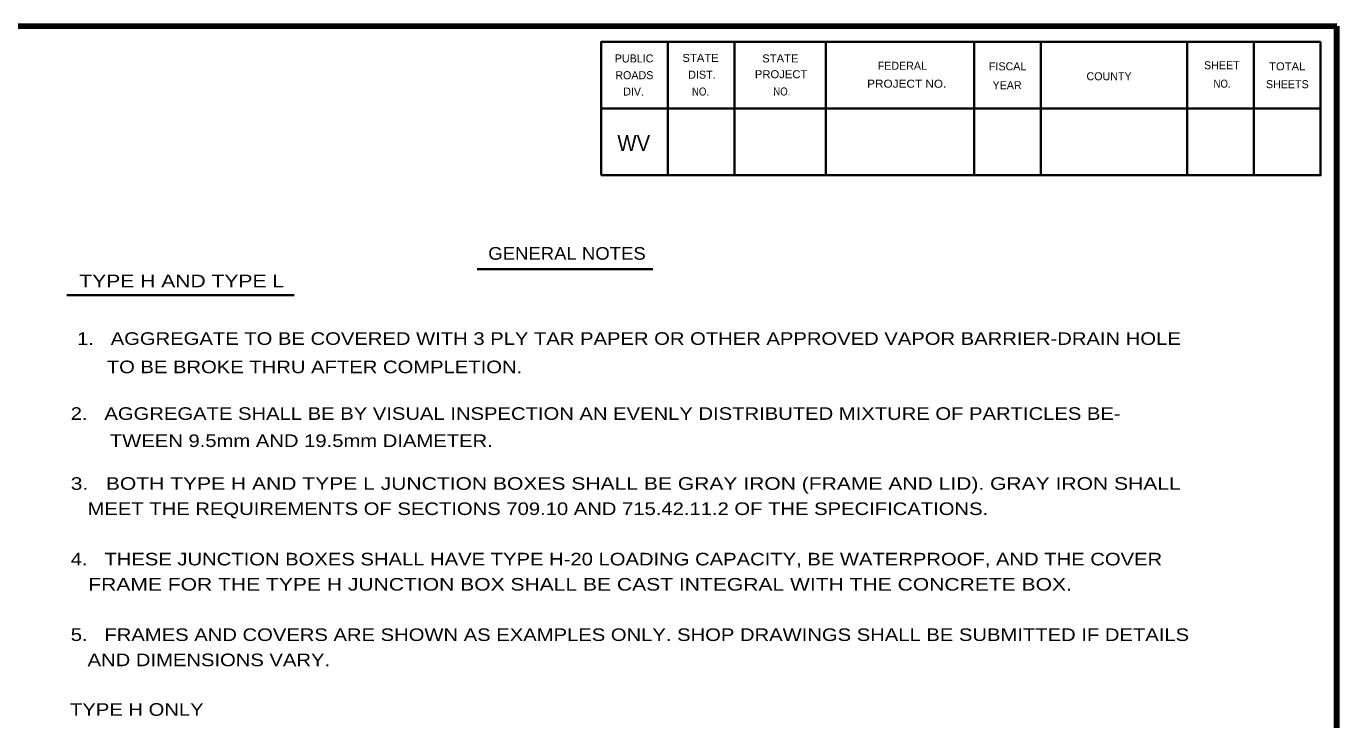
# Model space of a CAD drawing. Extents: x 442 to 1297, y -1132 to -588.
# Drawn here: x 1041 to 1290.7, y -726.2 to -594.1 of the extents above; entities that cross this region are included whole.
import ezdxf

# ---------------------------------------------------------------- set-up
doc = ezdxf.new("R2010")
doc.units = 0
doc.header["$LTSCALE"] = 0.96
doc.layers.add('1', color=7, linetype='Continuous', lineweight=35)
doc.layers.add('61', color=7, linetype='Continuous', lineweight=35)

msp = doc.modelspace()

# ---------------------------------------------------------------- linework, layer by layer
at = {"layer": '1', "lineweight": 158}
msp.add_line((1290.7447, -1120.1679), (1290.7447, -594.0679), dxfattribs=at)
at = {"layer": '1', "lineweight": 13}
msp.add_line((1290.7447, -1120.1679), (1290.7447, -594.0679), dxfattribs=at)
at = {"layer": '1'}
for p, q in [((1126.9354, -640.3295), (1160.3767, -640.3295)), ((1048.7097, -645.2843), (1092.0302, -645.2843))]:
    msp.add_line(p, q, dxfattribs=at)
at = {"layer": '1', "lineweight": 158}
msp.add_lwpolyline([(1290.7447, -594.0679), (499.0447, -594.1679), (499.1447, -1120.1679)], dxfattribs=at)
at = {"layer": '61'}
for p, q in [((1163.2447, -597.0679), (1163.2447, -622.4679)), ((1175.9447, -597.0679), (1175.9447, -622.4679)), ((1193.3447, -597.0679), (1193.3447, -622.4679)), ((1221.6447, -597.0679), (1221.6447, -622.4679)), ((1234.3447, -597.0679), (1234.3447, -622.4679)), ((1262.2447, -597.0679), (1262.2447, -622.4679)), ((1274.9447, -597.0679), (1274.9447, -622.4679)), ((1287.6447, -609.7679), (1150.5447, -609.7679))]:
    msp.add_line(p, q, dxfattribs=at)
for points in [[(1287.6447, -597.0679), (1150.5447, -597.0679), (1150.5447, -622.4679)], [(1287.6447, -597.0679), (1287.6447, -622.4679), (1150.5447, -622.4679)]]:
    msp.add_lwpolyline(points, dxfattribs=at)

# ---------------------------------------------------------------- texts
at = {"layer": '1'}
for s, height, width, p in [('WV', 3.048, 0.95, (1153.6447, -617.8679)), ('GENERAL NOTES', 2.4, 1.1, (1129.0254, -638.5495)), ('TYPE H AND TYPE L', 2.4, 1.25, (1051.0982, -643.8028)), ('1.   AGGREGATE TO BE COVERED WITH 3 PLY TAR PAPER OR OTHER APPROVED VAPOR BARRIER-DRAIN HOLE', 2.4, 1.2, (1050.6505, -654.7757)), ('TO BE BROKE THRU AFTER COMPLETION.', 2.4, 1.2, (1056.3233, -660.1728)), ('2.   AGGREGATE SHALL BE BY VISUAL INSPECTION AN EVENLY DISTRIBUTED MIXTURE OF PARTICLES BE-', 2.4, 1.2, (1049.4543, -669.0629)), ('TWEEN 9.5mm AND 19.5mm DIAMETER.', 2.4, 1.2, (1056.92, -674.2358)), ('3.   BOTH TYPE H AND TYPE L JUNCTION BOXES SHALL BE GRAY IRON (FRAME AND LID). GRAY IRON SHALL', 2.4, 1.25, (1049.4543, -682.3929)), ('   MEET THE REQUIREMENTS OF SECTIONS 709.10 AND 715.42.11.2 OF THE SPECIFICATIONS.', 2.4, 1.2, (1049.4543, -687.1929)), ('4.   THESE JUNCTION BOXES SHALL HAVE TYPE H-20 LOADING CAPACITY, BE WATERPROOF, AND THE COVER', 2.4, 1.2, (1049.4543, -696.7929)), ('   FRAME FOR THE TYPE H JUNCTION BOX SHALL BE CAST INTEGRAL WITH THE CONCRETE BOX.', 2.4, 1.25, (1049.4543, -701.5929)), ('5.   FRAMES AND COVERS ARE SHOWN AS EXAMPLES ONLY. SHOP DRAWINGS SHALL BE SUBMITTED IF DETAILS', 2.4, 1.2, (1049.4543, -711.1929)), ('   AND DIMENSIONS VARY.', 2.4, 1.2, (1049.4543, -715.9929)), ('TYPE H ONLY', 2.4, 1.2, (1049.3172, -725.4441))]:
    msp.add_text(s, height=height, dxfattribs=dict(at, width=width)).set_placement(p)
at = {"layer": '61'}
for s, height, rotation, p in [('PUBLIC', 1.525, 0.033, (1153.1447, -600.9679)), ('FEDERAL', 1.523, 0.007, (1203.2447, -602.3679)), ('FISCAL', 1.525, 359.942, (1224.4447, -602.4679)), ('SHEET', 1.525, 0.059, (1265.4447, -602.2679)), ('ROADS', 1.525, 0.124, (1153.2447, -604.1679)), ('DIST.', 1.525, 0.056, (1167.1447, -604.0679)), ('COUNTY', 1.523, 0.069, (1243.0447, -604.3679)), ('SHEETS', 1.523, 359.959, (1277.2447, -605.8679)), ('DIV.', 1.525, 359.932, (1154.7447, -607.2679)), ('YEAR', 1.523, 0.105, (1225.1447, -606.0679))]:
    msp.add_text(s, height=height, rotation=rotation, dxfattribs=at).set_placement(p)
for s, rotation, width, p in [('STATE', 0.059, 1.05, (1166.0447, -600.8679)), ('STATE', 0.059, 1.05, (1181.2447, -600.9679)), ('TOTAL', 359.926, 1.05, (1277.8447, -602.4679)), ('PROJECT', 359.908, 1.05, (1179.8447, -603.9679)), ('PROJECT NO.', 359.922, 1.1, (1201.2447, -605.7679)), ('NO.', 359.852, 0.9, (1267.2447, -605.7679)), ('NO.', 359.852, 0.9, (1167.8447, -607.2679)), ('NO.', 0.225, 0.9, (1183.3447, -607.2679))]:
    msp.add_text(s, height=1.525, rotation=rotation, dxfattribs=dict(at, width=width)).set_placement(p)

doc.saveas('drawing.dxf')
